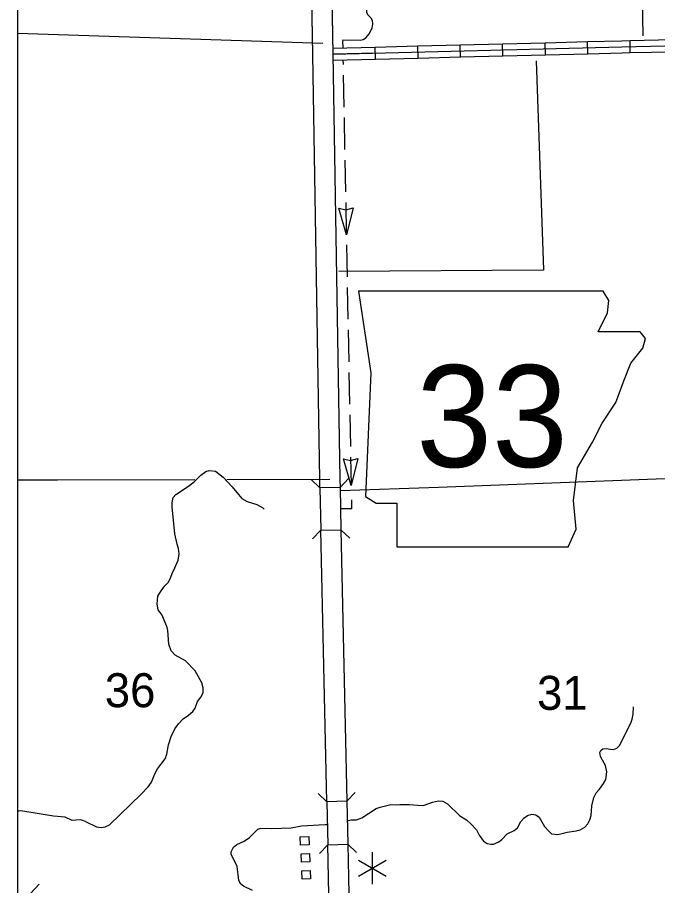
# Model space of a CAD drawing. Extents: x 1084508 to 1142749, y 1057638 to 1093403.
# Drawn here: x 1084508 to 1087007, y 1087680 to 1091069 of the extents above; entities that cross this region are included whole.
import ezdxf

# ---------------------------------------------------------------- set-up
doc = ezdxf.new("R2010")
doc.units = 0
for name, color, linetype in [('10', 7, 'Continuous'), ('32', 7, 'Continuous'), ('35', 7, 'Continuous'), ('37', 7, 'Continuous'), ('5', 7, 'Continuous'), ('56', 7, 'Continuous'), ('DSN_DRFT_Named-Boundary', 7, 'Continuous'), ('Level 10', 7, 'Continuous'), ('Level 21', 7, 'Continuous'), ('Level 32', 7, 'Continuous'), ('Level 35', 7, 'Continuous'), ('Level 37', 7, 'Continuous'), ('Level 43', 7, 'Continuous'), ('Level 48', 7, 'Continuous'), ('Level 5', 7, 'Continuous'), ('Level 7', 7, 'Continuous')]:
    doc.layers.add(name, color=color, linetype=linetype)

msp = doc.modelspace()

# ---------------------------------------------------------------- linework, layer by layer
at = {"layer": '10'}
for p, q in [((1085723.1, 1087645.7), (1085719.1, 1087840.1)), ((1085797.5, 1087842), (1085801.5, 1087646.6))]:
    msp.add_line(p, q, dxfattribs=at)
for points in [[(1085688.9, 1089233.1), (1085688.2, 1089265.5), (1085661.3, 1090923.9), (1085628.9, 1092728.8)], [(1085707.4, 1092730), (1085739.8, 1090925.2), (1085766.6, 1089267), (1085767.3, 1089234.8)], [(1085767.3, 1089234.8), (1085688.9, 1089233.1)], [(1085688.9, 1089233.1), (1085692.5, 1089068)], [(1085767.3, 1089234.8), (1085770.9, 1089069.6)], [(1085692.5, 1089068), (1085770.9, 1089069.6)], [(1085715.5, 1088007.9), (1085692.5, 1089068)], [(1085770.9, 1089069.6), (1085794, 1088009.7)], [(1085794, 1088009.7), (1085715.5, 1088007.9)], [(1085715.5, 1088007.9), (1085719.1, 1087840.1)], [(1085794, 1088009.7), (1085797.5, 1087842)], [(1085719.1, 1087840.1), (1085797.5, 1087842)]]:
    msp.add_lwpolyline(points, dxfattribs=at)
at = {"layer": '32'}
msp.add_lwpolyline([(1085908.9, 1090929.9), (1085739.8, 1090925.5)], dxfattribs=at)
at = {"layer": '35'}
for points in [[(1085112.5, 1088898.6), (1085123.1, 1088920.4), (1085134.9, 1088950.1), (1085139, 1088975.5), (1085136.6, 1088996.5), (1085131.6, 1089012.7), (1085122.5, 1089053.4), (1085111.7, 1089158.7), (1085111.7, 1089175.1), (1085116, 1089195.4), (1085126.9, 1089207.2), (1085176.1, 1089239.9), (1085199.3, 1089257.8), (1085223.9, 1089282.6), (1085243.2, 1089296.9), (1085257, 1089300.3), (1085281.4, 1089298.1), (1085311.4, 1089275.2), (1085346.9, 1089236.5), (1085371, 1089206.9), (1085383.5, 1089191.3), (1085405, 1089179.8)], [(1085405, 1089179.8), (1085442.6, 1089167.4), (1085465.8, 1089154.4), (1085471.4, 1089150)], [(1085233, 1088434.1), (1085233.3, 1088452.7), (1085227.9, 1088471.4), (1085202.2, 1088518.3), (1085163.9, 1088557.2), (1085124, 1088580.3), (1085108.6, 1088596.7), (1085098.8, 1088622.8), (1085095.6, 1088676.5), (1085092.6, 1088688.1), (1085072.6, 1088735.5), (1085057.6, 1088756.7), (1085052.9, 1088779.1), (1085056.6, 1088809.6), (1085069.1, 1088830.8), (1085084.1, 1088850.3), (1085097.4, 1088864.6), (1085107.4, 1088884.5), (1085112.5, 1088898.6)], [(1084774.3, 1087930.3), (1084816.6, 1087910.4), (1084835, 1087906.7), (1084850.1, 1087909.2), (1084867, 1087917.3), (1084991.4, 1088037.3), (1085018.7, 1088065.4), (1085031.9, 1088083.6), (1085044.5, 1088116.2), (1085055.1, 1088136.1), (1085084.5, 1088175.6), (1085090.8, 1088193.5), (1085097.6, 1088230), (1085107.8, 1088262.2), (1085122.7, 1088292.3), (1085137.4, 1088312.4), (1085155, 1088331.3), (1085175.9, 1088345.3), (1085193.3, 1088359.8), (1085201.9, 1088372.5), (1085211, 1088398.9), (1085224.8, 1088417.1), (1085233, 1088434.1)], [(1084774.3, 1087930.3), (1084755.7, 1087937.2), (1084736, 1087935.6), (1084722.2, 1087934.1), (1084694.5, 1087947.3), (1084649.4, 1087951.3), (1084537.7, 1087969.9), (1084521.6, 1087971.9), (1084512.5, 1087971.2), (1084507.9, 1087969.3)], [(1085425.4, 1087661.9), (1085390.1, 1087678.6), (1085379.5, 1087686), (1085372.9, 1087700.9), (1085365.4, 1087755.3), (1085342.7, 1087803.7), (1085343, 1087811.9), (1085351.7, 1087830.4), (1085364, 1087840.4), (1085393.1, 1087853.5), (1085413.9, 1087868.8), (1085446.4, 1087900.1), (1085457.6, 1087904.7), (1085501.5, 1087903.5), (1085576.9, 1087906.4), (1085616.7, 1087913.2), (1085709.3, 1087918.5)], [(1085709.3, 1087918.5), (1085717.2, 1087918.8)]]:
    msp.add_lwpolyline(points, dxfattribs=at)
at = {"layer": '37'}
for points in [[(1085688.9, 1089233.1), (1085654.9, 1089265.7)], [(1085799.9, 1089268.8), (1085767.3, 1089234.8)], [(1085659.9, 1089034), (1085692.5, 1089068)], [(1085770.9, 1089069.6), (1085804.9, 1089037.1)], [(1085715.5, 1088007.9), (1085681.5, 1088040.4)], [(1085826.5, 1088043.8), (1085794, 1088009.7)], [(1085686.6, 1087806.1), (1085719.1, 1087840.1)], [(1085797.5, 1087842), (1085831.6, 1087809.4)], [(1084559.9, 1087651.4), (1084592.6, 1087685.4)]]:
    msp.add_lwpolyline(points, dxfattribs=at)
at = {"layer": '5'}
for p, q in [((1084507.9, 1091007.8), (1085699.6, 1090968.6)), ((1084507.9, 1089264.3), (1084665, 1089263.7))]:
    msp.add_line(p, q, dxfattribs=at)
for points in [[(1084665, 1089263.7), (1085200.9, 1089265)], [(1085324.8, 1089265.3), (1085727.4, 1089266.2)]]:
    msp.add_lwpolyline(points, dxfattribs=at)
at = {"layer": '56'}
for points in [[(1085613.5, 1087838.3), (1085612.3, 1087871), (1085645.1, 1087872.2), (1085646.3, 1087839.5)], [(1085616.7, 1087771.8), (1085615.4, 1087804.4), (1085648.2, 1087805.6), (1085649.4, 1087773)], [(1085619.4, 1087705.7), (1085618.1, 1087738.4), (1085650.9, 1087739.6), (1085652.1, 1087707)]]:
    msp.add_lwpolyline(points, close=True, dxfattribs=at)
at = {"layer": 'DSN_DRFT_Named-Boundary'}
msp.add_lwpolyline([(1084507.9, 1057640), (1142749.2, 1057640), (1142749.2, 1093403.4), (1084507.9, 1093403.4)], close=True, dxfattribs=at)
at = {"layer": 'Level 10'}
for p, q in [((1085767.3, 1089234.8), (1085688.9, 1089233.1)), ((1085723.1, 1087645.7), (1085719.1, 1087840.1)), ((1085797.5, 1087842), (1085801.5, 1087646.6))]:
    msp.add_line(p, q, dxfattribs=at)
for points in [[(1085688.9, 1089233.1), (1085688.2, 1089265.5), (1085661.3, 1090923.9), (1085618.1, 1093331.7), (1085616.1, 1093403.4)], [(1085694.6, 1093403.4), (1085696.5, 1093333.4), (1085739.8, 1090925.2), (1085766.6, 1089267), (1085767.3, 1089234.8)], [(1085688.9, 1089233.1), (1085692.5, 1089068)], [(1085767.3, 1089234.8), (1085770.9, 1089069.6)], [(1085692.5, 1089068), (1085770.9, 1089069.6)], [(1085715.5, 1088007.9), (1085692.5, 1089068)], [(1085770.9, 1089069.6), (1085794, 1088009.7)], [(1085794, 1088009.7), (1085715.5, 1088007.9)], [(1085715.5, 1088007.9), (1085719.1, 1087840.1)], [(1085794, 1088009.7), (1085797.5, 1087842)], [(1085719.1, 1087840.1), (1085797.5, 1087842)]]:
    msp.add_lwpolyline(points, dxfattribs=at)
at = {"layer": 'Level 21'}
msp.add_lwpolyline([(1085839.7, 1090001.1), (1085887.5, 1089682.4), (1085866.2, 1089199.2), (1085908.7, 1089172.7), (1085988.4, 1089172.7), (1085988.4, 1089002.7), (1086657.5, 1089002.7), (1086689.3, 1089071.8), (1086678.7, 1089183.3), (1086694.6, 1089310.7), (1086753, 1089411.6), (1086790.2, 1089486), (1086843.3, 1089565.6), (1086875.2, 1089650.6), (1086901.7, 1089719.6), (1086949.5, 1089778), (1086960.1, 1089815.2), (1086938.9, 1089841.7), (1086774.3, 1089841.7), (1086811.5, 1089916.1), (1086816.8, 1089963.9), (1086794.8, 1090000.6)], close=True, dxfattribs=at)
at = {"layer": 'Level 32'}
for p, q in [((1085906.1, 1090906.2), (1085904.9, 1090953.3)), ((1086071.8, 1090910.5), (1086070.6, 1090957.6)), ((1086237.4, 1090914.7), (1086236.2, 1090961.8)), ((1086403.1, 1090919), (1086401.9, 1090966)), ((1086568.8, 1090923.2), (1086567.6, 1090970.3)), ((1086734.5, 1090927.4), (1086733.3, 1090974.5)), ((1086900.1, 1090931.6), (1086899, 1090978.6))]:
    msp.add_line(p, q, dxfattribs=at)
for points in [[(1085739.2, 1090949.1), (1085904.9, 1090953.3)], [(1085739.8, 1090925.5), (1086867.7, 1090954.4), (1087371.7, 1090965.7), (1089097, 1090954.4)], [(1085904.9, 1090953.3), (1086070.6, 1090957.6)], [(1086070.6, 1090957.6), (1086236.2, 1090961.8)], [(1086236.2, 1090961.8), (1086401.9, 1090966)], [(1086401.9, 1090966), (1086567.6, 1090970.3)], [(1086567.6, 1090970.3), (1086733.3, 1090974.5)], [(1086733.3, 1090974.5), (1086867.1, 1090977.9), (1086899, 1090978.6)], [(1086899, 1090978.6), (1087064.7, 1090982.3)], [(1086237.4, 1090914.7), (1086403.1, 1090919)], [(1086403.1, 1090919), (1086568.8, 1090923.2)], [(1086568.8, 1090923.2), (1086734.5, 1090927.4)], [(1086734.5, 1090927.4), (1086868.2, 1090930.8), (1086900.1, 1090931.6)], [(1086900.1, 1090931.6), (1087065.7, 1090935.3)], [(1085740.2, 1090902), (1085906.1, 1090906.2)], [(1085906.1, 1090906.2), (1086071.8, 1090910.5)], [(1086071.8, 1090910.5), (1086237.4, 1090914.7)]]:
    msp.add_lwpolyline(points, dxfattribs=at)
at = {"layer": 'Level 35'}
for points in [[(1085777.1, 1090981), (1085845.2, 1090980.3), (1085858, 1090983), (1085868.5, 1090989.1), (1085882, 1091006.6), (1085892.8, 1091029), (1085895.1, 1091044.3), (1085894, 1091056.8), (1085888.6, 1091066.1), (1085875.6, 1091078.5), (1085871.4, 1091088.7), (1085871.6, 1091108.3), (1085878, 1091131.8), (1085895.9, 1091184.4)], [(1086779.5, 1088057.3), (1086796.1, 1088078.4), (1086804.3, 1088095.1), (1086808.5, 1088124.9), (1086803.8, 1088149.3), (1086797.5, 1088158.8), (1086783.3, 1088184.4), (1086781.8, 1088199.5), (1086785.6, 1088207.8), (1086793.5, 1088214.1), (1086805.8, 1088215.3), (1086821.9, 1088212.6), (1086834.6, 1088211.8), (1086847, 1088217), (1086858.6, 1088226.9), (1086901.9, 1088314.2), (1086907.2, 1088330.4), (1086911.9, 1088350.2), (1086912.8, 1088378.2)], [(1086398.9, 1087860.1), (1086419.8, 1087882.3), (1086446.7, 1087894.9), (1086459.8, 1087906.4), (1086473.4, 1087930.9), (1086484.3, 1087943.3), (1086498.4, 1087953.9), (1086516, 1087958.7), (1086532, 1087956.4), (1086544.6, 1087947.1), (1086564.9, 1087910.7), (1086581.9, 1087892.7), (1086593, 1087882.4), (1086617.3, 1087879.6), (1086654.2, 1087888.5), (1086688.9, 1087893.6), (1086704.5, 1087898.6), (1086722.4, 1087908.7), (1086733.9, 1087921.1), (1086742.2, 1087936.5), (1086747.1, 1087953.7), (1086750.4, 1087992.3), (1086758.4, 1088024.1), (1086767.2, 1088042), (1086779.5, 1088057.3)], [(1085795.6, 1087933.6), (1085810.7, 1087937.3), (1085831.5, 1087937.4), (1085852.6, 1087944.5), (1085908.5, 1087981.2), (1085923.5, 1087986.5), (1085965.3, 1087996.6), (1085989.2, 1087995.9), (1086001.2, 1087997), (1086037.7, 1087996.5), (1086088.2, 1087993.3), (1086095.1, 1087994.8), (1086128, 1088006.5), (1086151.5, 1088011.5), (1086168.2, 1088009.5), (1086186.9, 1087999.5), (1086235.2, 1087953.1), (1086260.3, 1087936.8), (1086277.9, 1087921.7), (1086299.5, 1087898.5), (1086310.4, 1087876.9), (1086327.6, 1087854.2), (1086341.8, 1087845.3), (1086355.8, 1087842.1), (1086366.1, 1087842.8), (1086386.6, 1087851.4), (1086398.9, 1087860.1)]]:
    msp.add_lwpolyline(points, dxfattribs=at)
at = {"layer": 'Level 37'}
for p, q in [((1085754.7, 1088008.8), (1085754.7, 1088008.8)), ((1085758.3, 1087841), (1085758.3, 1087841))]:
    msp.add_line(p, q, dxfattribs=at)
for points in [[(1085688.9, 1089233.1), (1085654.9, 1089265.7)], [(1085799.9, 1089268.8), (1085767.3, 1089234.8)], [(1085659.9, 1089034), (1085692.5, 1089068)], [(1085770.9, 1089069.6), (1085804.9, 1089037.1)], [(1085715.5, 1088007.9), (1085681.5, 1088040.4)], [(1085826.5, 1088043.8), (1085794, 1088009.7)], [(1085686.6, 1087806.1), (1085719.1, 1087840.1)], [(1085797.5, 1087842), (1085831.6, 1087809.4)]]:
    msp.add_lwpolyline(points, dxfattribs=at)
at = {"layer": 'Level 43'}
for p, q in [((1085762.3, 1090324.4), (1085790.2, 1090317.5)), ((1085792.2, 1090220.9), (1085762.3, 1090324.4)), ((1085790.5, 1090317.5), (1085818.1, 1090325.5)), ((1085818.1, 1090325.5), (1085792.2, 1090220.9)), ((1085780.4, 1089345.9), (1085808.2, 1089339)), ((1085810.3, 1089242.4), (1085780.4, 1089345.9)), ((1085808.6, 1089339), (1085836.2, 1089347)), ((1085836.2, 1089347), (1085810.3, 1089242.4))]:
    msp.add_line(p, q, dxfattribs=at)
for points in [[(1085777.2, 1090977.1), (1085777.7, 1090950.6)], [(1085778.6, 1090902.8), (1085778.9, 1090885)], [(1085779.7, 1090843.6), (1085782.1, 1090719.3)], [(1085782.9, 1090677.9), (1085785.3, 1090553.6)], [(1085786.1, 1090512.2), (1085788.5, 1090387.9)], [(1085789.3, 1090346.5), (1085791.6, 1090222.2)], [(1085792.4, 1090180.8), (1085794.8, 1090056.5)], [(1085795.6, 1090015.1), (1085796.8, 1089952.9)], [(1085796.8, 1089952.9), (1085798, 1089890.8)], [(1085798.8, 1089849.4), (1085801.2, 1089725.1)], [(1085802, 1089683.7), (1085804.4, 1089559.4)], [(1085805.1, 1089518), (1085807.5, 1089393.7)], [(1085808.3, 1089352.3), (1085810.4, 1089242.8)], [(1085811.5, 1089186.6), (1085812.2, 1089151.1), (1085768.7, 1089150.6)]]:
    msp.add_lwpolyline(points, dxfattribs=at)
at = {"layer": 'Level 48'}
for p, q in [((1085893.5, 1087685.7), (1085893.5, 1087811.3)), ((1085839.1, 1087779.9), (1085947.8, 1087717.1)), ((1085839.1, 1087717.1), (1085947.8, 1087779.9))]:
    msp.add_line(p, q, dxfattribs=at)
at = {"layer": 'Level 5'}
msp.add_lwpolyline([(1088474.1, 1089289.8), (1087410.2, 1089282), (1086151.8, 1089234.2), (1085767.8, 1089221.6)], dxfattribs=at)
at = {"layer": 'Level 7'}
msp.add_line((1086923.9, 1092627.1), (1086949.3, 1090997.3), dxfattribs=at)
msp.add_lwpolyline([(1086533.2, 1090900.2), (1086561.6, 1090084.2), (1086561.7, 1090082.1), (1086560.2, 1090082.1), (1085762.6, 1090077.4)], dxfattribs=at)

# ---------------------------------------------------------------- texts
at = {"layer": '5'}
msp.add_text('36', height=132.58, dxfattribs=at).set_placement((1084849.3, 1088376.8))
at = {"layer": 'Level 21'}
msp.add_text('33', height=397.75, dxfattribs=at).set_placement((1086064.8, 1089314.2))
at = {"layer": 'Level 5'}
msp.add_text('31', height=132.58, dxfattribs=at).set_placement((1086536.3, 1088366.5))

doc.saveas('drawing.dxf')
